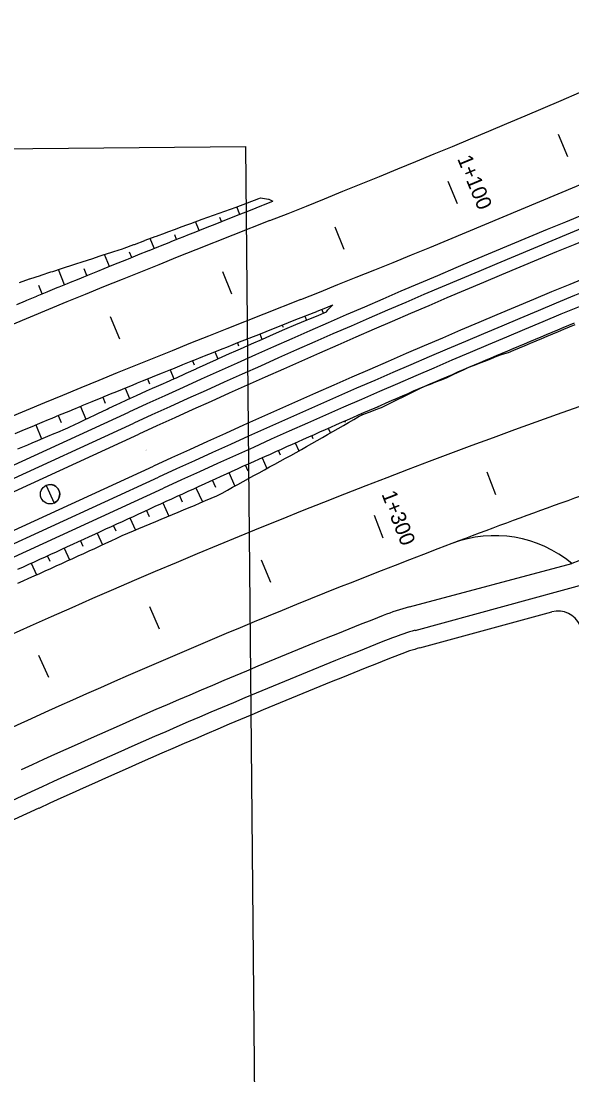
# Model space of a CAD drawing. Extents: x 6503541 to 6503743, y 5888004 to 5888145.
# Drawn here: x 6503620.887 to 6503621.981, y 5888061.951 to 5888064.041 of the extents above; entities that cross this region are included whole.
import ezdxf

# ---------------------------------------------------------------- set-up
doc = ezdxf.new("R2010")
doc.units = 0
doc.layers.add('12', color=7, linetype='Continuous')
doc.layers.add('tabela', color=7, linetype='Continuous')

msp = doc.modelspace()

# ---------------------------------------------------------------- linework, layer by layer
at = {"layer": '12'}
for p, q in [((6503621.3812, 5888063.645), (6503621.2344, 5888063.5868)), ((6503621.4432, 5888063.4889), (6503621.2963, 5888063.4306)), ((6503621.6294, 5888063.2909), (6503621.6305, 5888063.2883)), ((6503621.6626, 5888063.3047), (6503621.6624, 5888063.3052)), ((6503617.6711, 5888061.6924), (6503621.1014, 5888063.2651)), ((6503621.5972, 5888063.2746), (6503621.5964, 5888063.2766)), ((6503605.1366, 5888055.919), (6503621.1114, 5888063.2433)), ((6503621.5317, 5888063.2449), (6503621.5304, 5888063.2477)), ((6503621.5634, 5888063.2622), (6503621.5645, 5888063.2595)), ((6503621.4975, 5888063.2332), (6503621.5016, 5888063.2238)), ((6503605.1466, 5888055.8972), (6503621.1214, 5888063.2215)), ((6503621.4316, 5888063.2041), (6503621.4387, 5888063.1882)), ((6503621.4673, 5888063.2123), (6503621.4645, 5888063.2187)), ((6503621.4029, 5888063.1801), (6503621.3987, 5888063.1894)), ((6503621.3384, 5888063.1481), (6503621.333, 5888063.16)), ((6503621.3659, 5888063.1747), (6503621.3754, 5888063.1535)), ((6503605.1756, 5888055.8339), (6503621.1505, 5888063.1582)), ((6503621.3002, 5888063.1452), (6503621.3122, 5888063.1187)), ((6503605.1856, 5888055.8121), (6503621.1605, 5888063.1364)), ((6503621.274, 5888063.1159), (6503621.2674, 5888063.1303)), ((6503617.8058, 5888061.5719), (6503621.1705, 5888063.1146)), ((6503621.2082, 5888063.0867), (6503621.2019, 5888063.1005)), ((6503621.2347, 5888063.1154), (6503621.2476, 5888063.0871)), ((6503621.1692, 5888063.0855), (6503621.1812, 5888063.0591)), ((6503621.1037, 5888063.0555), (6503621.1148, 5888063.0314)), ((6503621.1422, 5888063.0579), (6503621.1364, 5888063.0705)), ((6503621.0763, 5888063.0289), (6503621.071, 5888063.0405)), ((6503621.0383, 5888063.0255), (6503621.049, 5888063.0021)), ((6503620.9728, 5888062.9955), (6503620.9835, 5888062.9721)), ((6503621.0109, 5888062.9987), (6503621.0055, 5888063.0105)), ((6503620.9454, 5888062.9689), (6503620.9401, 5888062.9805)), ((6503620.9074, 5888062.9655), (6503620.9179, 5888062.9425)), ((6503621.6586, 5888062.879), (6503621.9812, 5888062.965)), ((6503621.67, 5888062.8325), (6503622.0178, 5888062.9272)), ((6503621.6794, 5888062.7978), (6503621.9412, 5888062.869)), ((6503620.9074, 5888062.5122), (6503619.972, 5888062.0833)), ((6503620.9225, 5888062.4795), (6503619.987, 5888062.0506))]:
    msp.add_line(p, q, dxfattribs=at)
for points in [[(6503621.9731, 5888063.7715), (6503621.9543, 5888063.8157)], [(6503621.7349, 5888063.7236), (6503621.7533, 5888063.6792)], [(6503620.879, 5888063.479), (6503620.8962, 5888063.4861), (6503620.8991, 5888063.4873), (6503620.9185, 5888063.4953), (6503620.9192, 5888063.4956), (6503620.9394, 5888063.5039), (6503620.9408, 5888063.5045), (6503620.9595, 5888063.5121), (6503620.9631, 5888063.5136), (6503620.9797, 5888063.5204), (6503620.9854, 5888063.5228), (6503620.9998, 5888063.5286), (6503621.0078, 5888063.5319), (6503621.02, 5888063.5369), (6503621.0301, 5888063.541), (6503621.0402, 5888063.5451), (6503621.0524, 5888063.55), (6503621.0603, 5888063.5532), (6503621.0748, 5888063.5591), (6503621.0805, 5888063.5614), (6503621.0972, 5888063.5681), (6503621.1007, 5888063.5695), (6503621.1195, 5888063.5771), (6503621.1209, 5888063.5777), (6503621.1411, 5888063.5858), (6503621.1419, 5888063.5861), (6503621.1613, 5888063.5939), (6503621.1643, 5888063.5951), (6503621.1815, 5888063.6019), (6503621.1867, 5888063.604), (6503621.2018, 5888063.61), (6503621.2091, 5888063.6129), (6503621.222, 5888063.618), (6503621.2315, 5888063.6218), (6503621.2538, 5888063.6306), (6503621.2761, 5888063.6395), (6503621.2984, 5888063.6483), (6503621.3207, 5888063.6572), (6503621.343, 5888063.666), (6503621.3654, 5888063.6749), (6503621.3688, 5888063.6762), (6503621.3876, 5888063.6837)], [(6503620.8846, 5888063.5223), (6503620.9045, 5888063.5294), (6503620.9052, 5888063.5296), (6503620.926, 5888063.5364), (6503620.9275, 5888063.5369), (6503620.9468, 5888063.5432), (6503620.9505, 5888063.5444), (6503620.9676, 5888063.55), (6503620.9735, 5888063.5519), (6503620.9883, 5888063.5568), (6503620.9965, 5888063.5594), (6503621.0091, 5888063.5635), (6503621.0196, 5888063.5669), (6503621.0299, 5888063.5702), (6503621.0426, 5888063.5743), (6503621.0507, 5888063.5769), (6503621.0656, 5888063.5817), (6503621.0715, 5888063.5836), (6503621.0887, 5888063.5891), (6503621.0923, 5888063.5904), (6503621.1113, 5888063.5975), (6503621.1127, 5888063.598), (6503621.1331, 5888063.6057), (6503621.134, 5888063.606), (6503621.1536, 5888063.6133), (6503621.1566, 5888063.6144), (6503621.174, 5888063.6209), (6503621.1792, 5888063.6228), (6503621.1944, 5888063.6284), (6503621.2019, 5888063.6312), (6503621.2149, 5888063.636), (6503621.2245, 5888063.6395), (6503621.247, 5888063.6478), (6503621.2695, 5888063.656), (6503621.2922, 5888063.664), (6503621.3148, 5888063.672), (6503621.3373, 5888063.6805), (6503621.3598, 5888063.689), (6503621.3632, 5888063.6903), (6503621.3785, 5888063.6873), (6503621.3797, 5888063.6878), (6503621.3876, 5888063.6837)], [(6503621.3216, 5888063.6575), (6503621.3157, 5888063.6723)], [(6503621.241, 5888063.6256), (6503621.2341, 5888063.6431)], [(6503621.2857, 5888063.6433), (6503621.2824, 5888063.6514)], [(6503621.5291, 5888063.5878), (6503621.5112, 5888063.6323)], [(6503621.1518, 5888063.5901), (6503621.144, 5888063.6097)], [(6503621.1964, 5888063.6079), (6503621.1927, 5888063.6171)], [(6503621.0628, 5888063.5542), (6503621.0533, 5888063.5778)], [(6503621.1073, 5888063.5722), (6503621.1031, 5888063.5825)], [(6503620.9739, 5888063.518), (6503620.9616, 5888063.5481)], [(6503621.0183, 5888063.5362), (6503621.0129, 5888063.5496)], [(6503621.306, 5888063.499), (6503621.2883, 5888063.5436)], [(6503620.9295, 5888063.4998), (6503620.9226, 5888063.5164)], [(6503620.8759, 5888063.2228), (6503620.8894, 5888063.2285), (6503620.8979, 5888063.232), (6503620.9093, 5888063.2368), (6503620.9199, 5888063.2412), (6503620.9292, 5888063.2451), (6503620.942, 5888063.2504), (6503620.9491, 5888063.2534), (6503620.964, 5888063.2596), (6503620.9691, 5888063.2617), (6503620.9861, 5888063.2687), (6503620.989, 5888063.2699), (6503621.0082, 5888063.2778), (6503621.0089, 5888063.2781), (6503621.0288, 5888063.2864), (6503621.0302, 5888063.2869), (6503621.0488, 5888063.2945), (6503621.0523, 5888063.296), (6503621.0687, 5888063.3027), (6503621.0744, 5888063.3051), (6503621.0887, 5888063.3109), (6503621.0966, 5888063.3141), (6503621.1087, 5888063.319), (6503621.1187, 5888063.3231), (6503621.1286, 5888063.3271), (6503621.1408, 5888063.3321), (6503621.1486, 5888063.3352), (6503621.1629, 5888063.341), (6503621.1686, 5888063.3433), (6503621.1851, 5888063.35), (6503621.1886, 5888063.3514), (6503621.2072, 5888063.3589), (6503621.2086, 5888063.3594), (6503621.2286, 5888063.3675), (6503621.2294, 5888063.3678), (6503621.2486, 5888063.3755), (6503621.2516, 5888063.3766), (6503621.2686, 5888063.3835), (6503621.2738, 5888063.3855), (6503621.2887, 5888063.3914), (6503621.296, 5888063.3943), (6503621.3087, 5888063.3994), (6503621.3182, 5888063.4032), (6503621.3405, 5888063.412), (6503621.3628, 5888063.4208), (6503621.3851, 5888063.4297), (6503621.4074, 5888063.4385), (6503621.4297, 5888063.4474), (6503621.4521, 5888063.4562), (6503621.4555, 5888063.4576), (6503621.4745, 5888063.4651), (6503621.4757, 5888063.4656), (6503621.496, 5888063.4737), (6503621.4969, 5888063.474), (6503621.5065, 5888063.4779)], [(6503620.8813, 5888063.1923), (6503620.8875, 5888063.195), (6503620.9011, 5888063.2007), (6503620.9095, 5888063.2043), (6503620.9209, 5888063.2091), (6503620.9315, 5888063.2135), (6503620.9408, 5888063.2174), (6503620.9535, 5888063.2228), (6503620.9606, 5888063.2258), (6503620.9755, 5888063.232), (6503620.9804, 5888063.2342), (6503620.9971, 5888063.2422), (6503620.9999, 5888063.2435), (6503621.0187, 5888063.2524), (6503621.0194, 5888063.2527), (6503621.0389, 5888063.262), (6503621.0402, 5888063.2626), (6503621.0584, 5888063.2712), (6503621.0618, 5888063.2728), (6503621.0779, 5888063.2804), (6503621.0835, 5888063.283), (6503621.0974, 5888063.2895), (6503621.1051, 5888063.2932), (6503621.117, 5888063.2985), (6503621.1269, 5888063.3029), (6503621.1367, 5888063.3073), (6503621.1487, 5888063.3126), (6503621.1564, 5888063.316), (6503621.1705, 5888063.3222), (6503621.1761, 5888063.3247), (6503621.1924, 5888063.3319), (6503621.1958, 5888063.3334), (6503621.2141, 5888063.3417), (6503621.2155, 5888063.3423), (6503621.2351, 5888063.3513), (6503621.2359, 5888063.3516), (6503621.2547, 5888063.3602), (6503621.2576, 5888063.3615), (6503621.2744, 5888063.3691), (6503621.2794, 5888063.3714), (6503621.294, 5888063.378), (6503621.3012, 5888063.3812), (6503621.3137, 5888063.3867), (6503621.3231, 5888063.3909), (6503621.3451, 5888063.4005), (6503621.367, 5888063.4102), (6503621.389, 5888063.4199), (6503621.411, 5888063.4296), (6503621.4331, 5888063.4389), (6503621.4553, 5888063.448), (6503621.4587, 5888063.4494), (6503621.4776, 5888063.4572), (6503621.4789, 5888063.4577), (6503621.4936, 5888063.4639), (6503621.4965, 5888063.4684), (6503621.5065, 5888063.4779)], [(6503621.0834, 5888063.4098), (6503621.0653, 5888063.4543)], [(6503621.4508, 5888063.4557), (6503621.454, 5888063.4475)], [(6503621.4846, 5888063.4691), (6503621.4876, 5888063.4614)], [(6503620.8813, 5888062.9535), (6503620.8922, 5888062.9585), (6503620.9032, 5888062.9635), (6503620.9141, 5888062.9685), (6503620.925, 5888062.9735), (6503620.9359, 5888062.9785), (6503620.9468, 5888062.9835), (6503620.9577, 5888062.9885), (6503620.9686, 5888062.9935), (6503620.9795, 5888062.9985), (6503620.9904, 5888063.0035), (6503621.0013, 5888063.0085), (6503621.0122, 5888063.0135), (6503621.0231, 5888063.0185), (6503621.034, 5888063.0235), (6503621.045, 5888063.0285), (6503621.0559, 5888063.0335), (6503621.0668, 5888063.0385), (6503621.0777, 5888063.0435), (6503621.0886, 5888063.0485), (6503621.0995, 5888063.0535), (6503621.1104, 5888063.0585), (6503621.1213, 5888063.0635), (6503621.1322, 5888063.0685), (6503621.1431, 5888063.0735), (6503621.154, 5888063.0785), (6503621.1649, 5888063.0835), (6503621.1759, 5888063.0886), (6503621.1867, 5888063.0935), (6503621.1976, 5888063.0985), (6503621.2085, 5888063.1035), (6503621.2193, 5888063.1084), (6503621.2302, 5888063.1134), (6503621.2411, 5888063.1184), (6503621.2519, 5888063.1233), (6503621.2628, 5888063.1282), (6503621.2737, 5888063.1332), (6503621.2846, 5888063.1381), (6503621.2955, 5888063.143), (6503621.3063, 5888063.1479), (6503621.3172, 5888063.1529), (6503621.3281, 5888063.1578), (6503621.339, 5888063.1627), (6503621.3499, 5888063.1676), (6503621.3608, 5888063.1725), (6503621.3717, 5888063.1773), (6503621.3826, 5888063.1822), (6503621.3935, 5888063.1871), (6503621.4044, 5888063.192), (6503621.4153, 5888063.1968), (6503621.4263, 5888063.2017), (6503621.4372, 5888063.2065), (6503621.4481, 5888063.2114), (6503621.459, 5888063.2162), (6503621.4699, 5888063.2211), (6503621.4809, 5888063.2259), (6503621.4918, 5888063.2307), (6503621.5027, 5888063.2356), (6503621.5136, 5888063.2404), (6503621.5246, 5888063.2452), (6503621.5355, 5888063.25), (6503621.5465, 5888063.2548), (6503621.5574, 5888063.2596), (6503621.5683, 5888063.2644), (6503621.5793, 5888063.2691), (6503621.5902, 5888063.2739), (6503621.6012, 5888063.2787), (6503621.6121, 5888063.2835), (6503621.6231, 5888063.2882), (6503621.6341, 5888063.293), (6503621.645, 5888063.2977), (6503621.656, 5888063.3025), (6503621.6669, 5888063.3072), (6503621.6779, 5888063.3119), (6503621.6889, 5888063.3167), (6503621.6999, 5888063.3214), (6503621.7108, 5888063.3261), (6503621.7218, 5888063.3308), (6503621.7328, 5888063.3355), (6503621.7438, 5888063.3402), (6503621.7548, 5888063.3449), (6503621.7657, 5888063.3496), (6503621.7767, 5888063.3543), (6503621.7877, 5888063.359), (6503621.7987, 5888063.3636), (6503621.8097, 5888063.3683), (6503621.8207, 5888063.373), (6503621.8317, 5888063.3776), (6503621.8427, 5888063.3823), (6503621.8537, 5888063.3869), (6503621.8647, 5888063.3916), (6503621.8757, 5888063.3962), (6503621.8868, 5888063.4008), (6503621.8978, 5888063.4054), (6503621.9088, 5888063.4101), (6503621.9198, 5888063.4147), (6503621.9308, 5888063.4193), (6503621.9419, 5888063.4239), (6503621.9529, 5888063.4285), (6503621.9639, 5888063.4331), (6503621.9749, 5888063.4377), (6503621.986, 5888063.4422)], [(6503621.4061, 5888063.438), (6503621.4079, 5888063.4335)], [(6503621.7768, 5888063.3542), (6503621.7879, 5888063.3586), (6503621.799, 5888063.3629), (6503621.8102, 5888063.3673), (6503621.8213, 5888063.3716), (6503621.8324, 5888063.376), (6503621.8436, 5888063.3801), (6503621.8551, 5888063.3836), (6503621.8661, 5888063.3882), (6503621.8771, 5888063.3929), (6503621.8882, 5888063.3975), (6503621.8992, 5888063.4021), (6503621.9102, 5888063.4067), (6503621.9212, 5888063.4113), (6503621.9322, 5888063.416), (6503621.9432, 5888063.4206), (6503621.9543, 5888063.4252), (6503621.9653, 5888063.4298), (6503621.9763, 5888063.4343), (6503621.9873, 5888063.4389)], [(6503621.3615, 5888063.4203), (6503621.3657, 5888063.4097)], [(6503621.3169, 5888063.4026), (6503621.3194, 5888063.3965)], [(6503621.2723, 5888063.3849), (6503621.2779, 5888063.3707)], [(6503621.1832, 5888063.3492), (6503621.1905, 5888063.331)], [(6503621.2277, 5888063.3671), (6503621.231, 5888063.359)], [(6503621.6889, 5888063.3166), (6503621.7001, 5888063.3209), (6503621.7112, 5888063.3252), (6503621.7224, 5888063.3295), (6503621.7333, 5888063.3342), (6503621.7442, 5888063.3393), (6503621.755, 5888063.3443), (6503621.7658, 5888063.3494), (6503621.7768, 5888063.3542)], [(6503621.1387, 5888063.3312), (6503621.1426, 5888063.3214)], [(6503620.8808, 5888062.9258), (6503620.8918, 5888062.9308), (6503620.9027, 5888062.9357), (6503620.9137, 5888062.9406), (6503620.9246, 5888062.9455), (6503620.9355, 5888062.9505), (6503620.9465, 5888062.9554), (6503620.9574, 5888062.9603), (6503620.9684, 5888062.9653), (6503620.9793, 5888062.9702), (6503620.9902, 5888062.9751), (6503621.0012, 5888062.98), (6503621.0121, 5888062.985), (6503621.023, 5888062.99), (6503621.0339, 5888062.9951), (6503621.0448, 5888063.0001), (6503621.0557, 5888063.0052), (6503621.0665, 5888063.0102), (6503621.0774, 5888063.0154), (6503621.0883, 5888063.0203), (6503621.0994, 5888063.025), (6503621.1105, 5888063.0296), (6503621.1216, 5888063.0342), (6503621.1326, 5888063.0388), (6503621.1437, 5888063.0435), (6503621.1548, 5888063.0481), (6503621.1659, 5888063.0527), (6503621.177, 5888063.0573), (6503621.188, 5888063.062), (6503621.1991, 5888063.0666), (6503621.2101, 5888063.0712), (6503621.2211, 5888063.0758), (6503621.2321, 5888063.0804), (6503621.2431, 5888063.0851), (6503621.254, 5888063.0899), (6503621.2649, 5888063.0947), (6503621.2759, 5888063.0995), (6503621.2868, 5888063.1044), (6503621.2971, 5888063.1104), (6503621.3076, 5888063.1162), (6503621.3181, 5888063.122), (6503621.3285, 5888063.1278), (6503621.339, 5888063.1335), (6503621.3495, 5888063.1393), (6503621.36, 5888063.1451), (6503621.3705, 5888063.1508), (6503621.381, 5888063.1566), (6503621.3915, 5888063.1623), (6503621.402, 5888063.1681), (6503621.4125, 5888063.1738), (6503621.4231, 5888063.1795), (6503621.4336, 5888063.1853), (6503621.444, 5888063.1912), (6503621.4545, 5888063.1971), (6503621.4649, 5888063.203), (6503621.4753, 5888063.2088), (6503621.4858, 5888063.2147), (6503621.4962, 5888063.2206), (6503621.5066, 5888063.2267), (6503621.517, 5888063.2328), (6503621.5274, 5888063.2388), (6503621.5378, 5888063.2449), (6503621.5481, 5888063.2509), (6503621.5585, 5888063.257), (6503621.5695, 5888063.2617), (6503621.5807, 5888063.266), (6503621.5918, 5888063.2703), (6503621.603, 5888063.2746), (6503621.6137, 5888063.2799), (6503621.6244, 5888063.2852), (6503621.6351, 5888063.2905), (6503621.6458, 5888063.2958), (6503621.6566, 5888063.3011), (6503621.6673, 5888063.3064), (6503621.6781, 5888063.3116), (6503621.6889, 5888063.3166)], [(6503621.0942, 5888063.3131), (6503621.1028, 5888063.2921)], [(6503621.0498, 5888063.2949), (6503621.0546, 5888063.2833)], [(6503621.0054, 5888063.2767), (6503621.016, 5888063.2511)], [(6503620.961, 5888063.2583), (6503620.9668, 5888063.2445)], [(6503620.9167, 5888063.2399), (6503620.9283, 5888063.2122)], [(6503621.8298, 5888063.1012), (6503621.8131, 5888063.1462)], [(6503620.9371, 5888063.1199), (6503620.9531, 5888063.0849)], [(6503621.5883, 5888063.0609), (6503621.6058, 5888063.0162)], [(6503621.3832, 5888062.9275), (6503621.365, 5888062.9719)], [(6503621.1621, 5888062.835), (6503621.1433, 5888062.8792)], [(6503620.9427, 5888062.7389), (6503620.9231, 5888062.7827)]]:
    msp.add_lwpolyline(points, dxfattribs=at)
msp.add_circle((6503620.9451, 5888063.1024), 0.0192, dxfattribs=at)
for centre, radius, start, end in [((6503612.5651, 5888085.8768), 23.916, 291.63106, 294.63086), ((6503612.5651, 5888085.8768), 24.084, 291.63127, 294.63089), ((6503631.1385, 5888041.3736), 24.0828, 111.63106, 114.63106), ((6503631.1385, 5888041.3736), 24.0588, 111.63106, 114.63106), ((6503631.1385, 5888041.3736), 24.0348, 111.63106, 114.63106), ((6503631.1385, 5888041.3736), 23.9652, 111.63106, 114.63106), ((6503631.1385, 5888041.3736), 23.9412, 111.63106, 114.63106), ((6503631.1385, 5888041.3736), 23.9172, 111.63106, 114.63106), ((6503630.1124, 5888041.1989), 24.084, 111.63106, 114.63106), ((6503630.1124, 5888041.1989), 23.916, 111.63106, 114.63106), ((6503626.819, 5888049.6188), 14.484, 108.92046, 114.63106), ((6503626.819, 5888049.6188), 14.316, 108.92046, 110.76715), ((6503620.9451, 5888063.1024), 0.0192, 350.1183, 114.5655), ((6503620.9451, 5888063.1024), 0.0192, 294.5655, 350.1183), ((6503626.819, 5888049.6188), 14.196, 108.96467, 109.92471), ((6503621.828, 5888062.7802), 0.24, 50.345, 110.7672), ((6503626.819, 5888049.6188), 14.316, 110.76718, 114.63106), ((6503621.7823, 5888062.4152), 0.48, 104.9281, 111.4848), ((6503621.9538, 5888062.8227), 0.048, 24.6311, 105.2302), ((6503626.819, 5888049.6188), 14.232, 111.48479, 114.63098), ((6503621.7834, 5888062.4157), 0.432, 105.2302, 111.4795), ((6503626.819, 5888049.6188), 14.184, 111.47952, 114.63098), ((6503626.819, 5888049.6188), 14.148, 111.47952, 114.63098), ((6503621.7834, 5888062.4157), 0.396, 105.2302, 111.4795)]:
    msp.add_arc(centre, radius, start, end, dxfattribs=at)
at = {"layer": 'tabela'}
for p, q in [((6503614.0979, 5888063.7245), (6503621.3333, 5888063.7921)), ((6503614.0979, 5888063.7245), (6503621.3333, 5888063.7921)), ((6503621.3333, 5888063.7921), (6503621.3802, 5888058.772)), ((6503621.3333, 5888063.7921), (6503621.3802, 5888058.772))]:
    msp.add_line(p, q, dxfattribs=at)

# ---------------------------------------------------------------- texts
at = {"layer": '12'}
for s, height, rotation, p in [('1+100', 0.03, 292.4861, (6503621.7531, 5888063.7678)), ('C', 0.0024, 24.6311, (6503621.1353, 5888063.1883)), ('1+300', 0.03, 291.2621, (6503621.6027, 5888063.1028))]:
    msp.add_text(s, height=height, rotation=rotation, dxfattribs=at).set_placement(p)

doc.saveas('drawing.dxf')
